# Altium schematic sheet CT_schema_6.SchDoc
size 372 x 336 mm
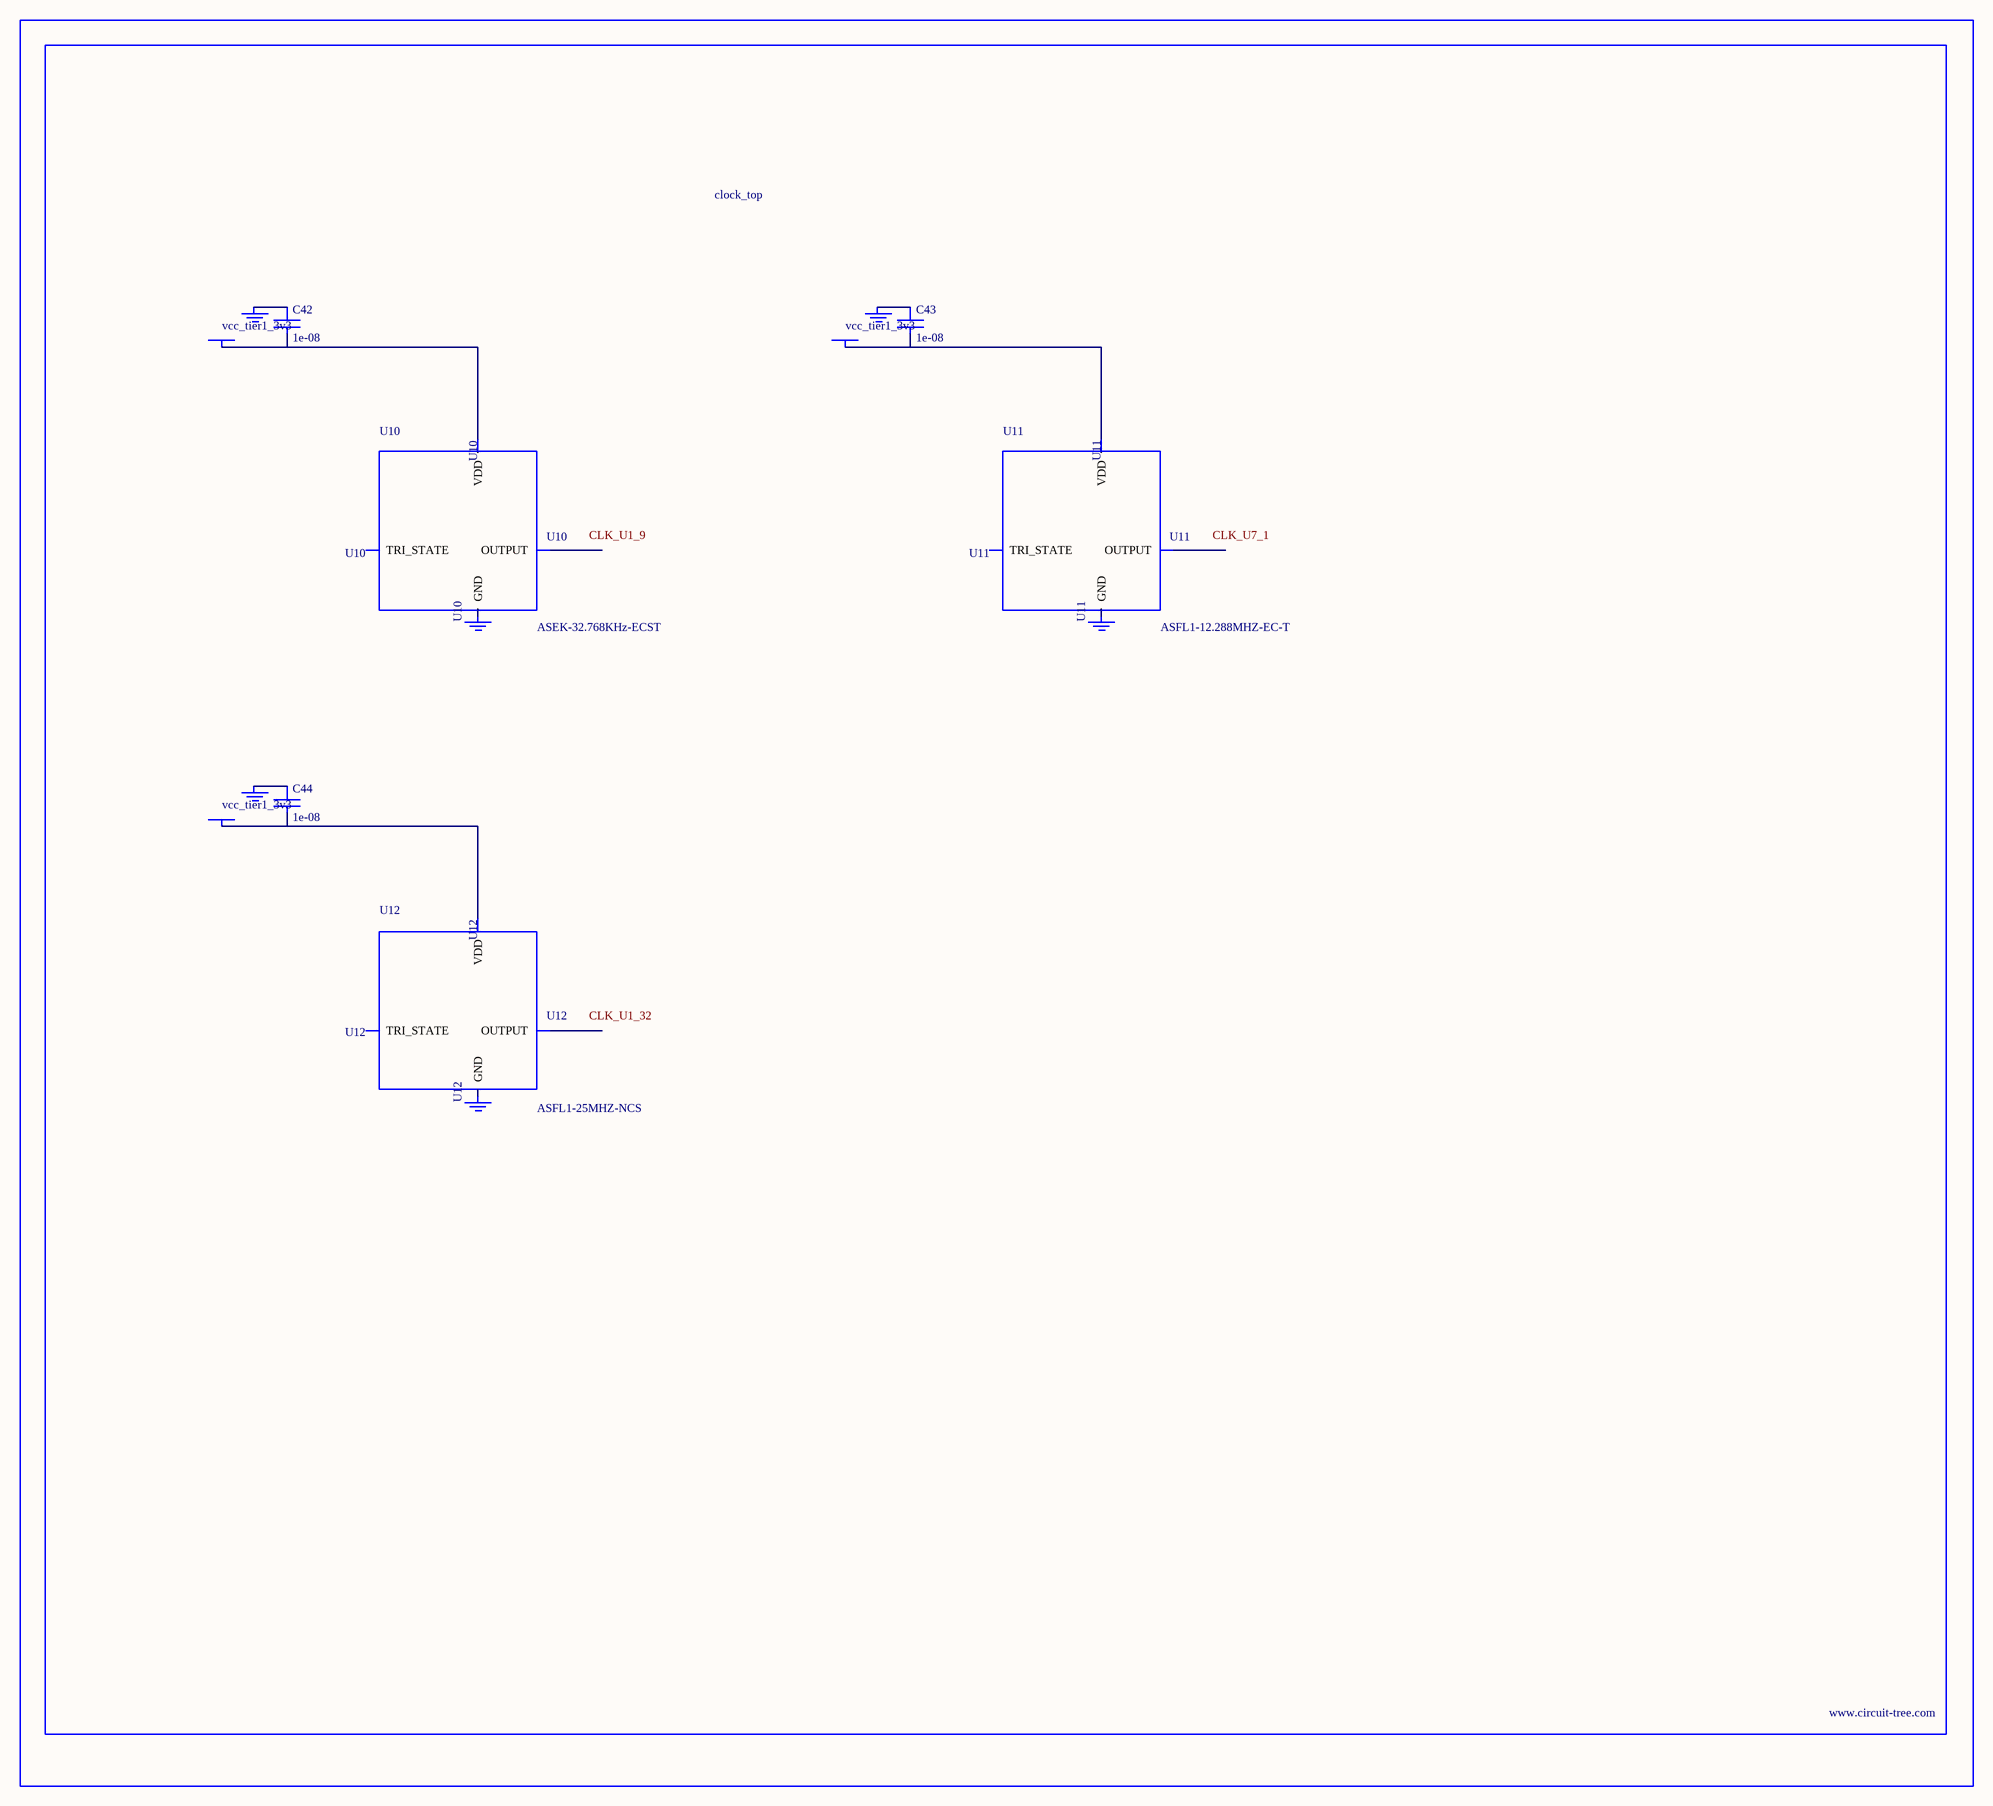
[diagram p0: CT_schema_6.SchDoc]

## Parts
BORDER5  (no value)
C42  1e-08  [C0402]
C43  1e-08  [C0402]
C44  1e-08  [C0402]
GND_INSTANCE_5_0  (no value)
GND_INSTANCE_5_1  (no value)
GND_INSTANCE_5_2  (no value)
GND_INSTANCE_5_3  (no value)
GND_INSTANCE_5_4  (no value)
GND_INSTANCE_5_5  (no value)
POWER_INSTANCE_5_0  vcc_tier1_3v3
POWER_INSTANCE_5_1  vcc_tier1_3v3
POWER_INSTANCE_5_2  vcc_tier1_3v3
U10  ASEK-32.768KHz-ECST  [ASEK]
U11  ASFL1-12.288MHZ-EC-T  [ASFL1]
U12  ASFL1-25MHZ-NCS  [ASFL1]

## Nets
NetC42_1: C42.1 GND_INSTANCE_5_0.0(GND)
NetC42_2: C42.2 POWER_INSTANCE_5_0.0(PWR) U10.4(VDD)
NetC43_1: C43.1 GND_INSTANCE_5_2.0(GND)
NetC43_2: C43.2 POWER_INSTANCE_5_1.0(PWR) U11.4(VDD)
NetC44_1: C44.1 GND_INSTANCE_5_4.0(GND)
NetC44_2: C44.2 POWER_INSTANCE_5_2.0(PWR) U12.4(VDD)

Not connected (* = marked no-connect by the designer): GND_INSTANCE_5_1 0(GND); GND_INSTANCE_5_3 0(GND); GND_INSTANCE_5_5 0(GND); U10 1(TRI_STATE) 2(GND) 3(OUTPUT); U11 1(TRI_STATE) 2(GND) 3(OUTPUT); U12 1(TRI_STATE) 2(GND) 3(OUTPUT)

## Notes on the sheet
- Labels drawn without touching a wire or pin: CLK_U1_9, CLK_U1_32, CLK_U7_1

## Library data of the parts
BORDER5 = BORDER_PAGE5
C42-C44 = C0402C103K3RAC
GND_INSTANCE_5_0-GND_INSTANCE_5_5 = GND
POWER_INSTANCE_5_0-POWER_INSTANCE_5_2 = PWR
